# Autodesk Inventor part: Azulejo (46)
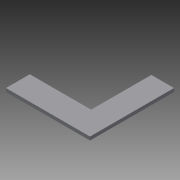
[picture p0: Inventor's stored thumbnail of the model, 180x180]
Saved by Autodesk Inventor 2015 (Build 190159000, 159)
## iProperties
Created: 2015-04
Part Number: Azulejo (46)
Material: Genérico
Document SubType Name: Modeling
Designer: Felipe
Density: 1 g/cm^3
Appearance: Padrão
Author: Felipe
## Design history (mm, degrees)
sketch "Sketch1"
  geometry: L1 (-5999.978, 1162.687)-(-5915.126, 1162.687); L2 (6980.022, 1162.687)-(6895.169, 1162.687); L3 (-1034.12, -6357.313)-(-1063.775, -6417.313); L4 (-5519.978, 1582.687)-(-6306.841, 1582.687); L5 (5000.022, -4857.313)-(6000.022, -4857.313); L6 (6000.022, -4857.313)-(6000.022, -6277.313); L7 (6000.022, -4837.313)-(5000.022, -4837.313); L8 (5000.022, -4837.313)-(5000.022, -3357.313); L9 (5000.022, -3357.313)-(6000.022, -3357.313); L10 (6000.022, -3357.313)-(6000.022, -4837.313); L11 (6000.022, -3337.313)-(5000.022, -3337.313); L12 (5000.022, -3337.313)-(5000.022, -1857.313); L13 (5000.022, -1857.313)-(6000.022, -1857.313); L14 (6000.022, -1857.313)-(6000.022, -3337.313); L15 (6000.022, -1837.313)-(5000.022, -1837.313); L16 (5000.022, -1837.313)-(5000.022, -357.313); L17 (5000.022, -357.313)-(6000.022, -357.313); L18 (6000.022, -357.313)-(6000.022, -1837.313); L19 (4000.022, -4837.313)-(3500.022, -4837.313); L20 (3500.022, -4837.313)-(3500.022, -3357.313); L21 (3500.022, -3357.313)-(4000.022, -3357.313); L22 (4000.022, -3357.313)-(4000.022, -4837.313); L23 (4000.022, -3337.313)-(3500.022, -3337.313); L24 (3500.022, -3337.313)-(3500.022, -1857.313); L25 (2000.022, 2662.687)-(2480.022, 2662.687); L26 (500.022, 2662.687)-(1980.022, 2662.687); L27 (-999.978, 2662.687)-(480.022, 2662.687); L28 (3500.022, -1857.313)-(4000.022, -1857.313); L29 (4000.022, -1857.313)-(4000.022, -3337.313); L30 (4000.022, -1837.313)-(3500.022, -1837.313); L31 (3500.022, -1837.313)-(3500.022, -357.313); L32 (3500.022, -357.313)-(4000.022, -357.313); L33 (4000.022, -357.313)-(4000.022, -1837.313); L34 (-5519.978, 1142.687)-(-5519.978, -337.313); L35 (6500.022, -337.313)-(6500.022, 1142.687); L36 (6480.022, 2662.687)-(5000.022, 2662.687); L37 (5000.022, 2642.687)-(6480.022, 2642.687); L38 (6480.022, 1142.687)-(6480.022, -337.313); L39 (6480.022, -337.313)-(5000.022, -337.313); L40 (5000.022, -337.313)-(5000.022, 1142.687); L41 (7965.922, 2662.687)-(6500.022, 2662.687); L42 (6500.022, 2642.687)-(7965.922, 2642.687); L43 (4980.022, 2662.687)-(3500.022, 2662.687); L44 (3500.022, 2642.687)-(4980.022, 2642.687); L45 (4980.022, 1142.687)-(4980.022, -337.313); L46 (4980.022, -337.313)-(3500.022, -337.313); L47 (3500.022, -337.313)-(3500.022, 1142.687); L48 (3500.022, -1837.313)-(3500.022, -357.313); L49 (3500.022, -3337.313)-(3500.022, -1857.313); L50 (3500.022, -4837.313)-(3500.022, -3357.313); L51 (3500.022, -6257.313)-(3500.022, -4857.313); L52 (4000.022, -6277.313)-(3500.022, -6277.313); L53 (3500.022, -6277.313)-(3500.022, -4857.313); L54 (3480.022, 1162.687)-(2000.022, 1162.687); L55 (2000.022, 1142.687)-(3480.022, 1142.687); L56 (3480.022, 1142.687)-(3480.022, -337.313); L57 (3480.022, -337.313)-(2000.022, -337.313); L58 (2000.022, -337.313)-(2000.022, 1142.687); L59 (3480.022, -357.313)-(3480.022, -1837.313); L60 (3480.022, -1857.313)-(3480.022, -3337.313); L61 (3480.022, -3357.313)-(3480.022, -4837.313); L62 (3480.022, -4857.313)-(3480.022, -6277.313); L63 (3500.022, -4857.313)-(4000.022, -4857.313); L64 (1980.022, 1162.687)-(500.022, 1162.687)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; 4 further points
  constraints: 1802 end point, 96 point on line, 2 other
extrude "Extrusion1" new body sketch "Sketch1" distance "d0" = 60; taper "d1" = 0 deg
body "Solid1"
